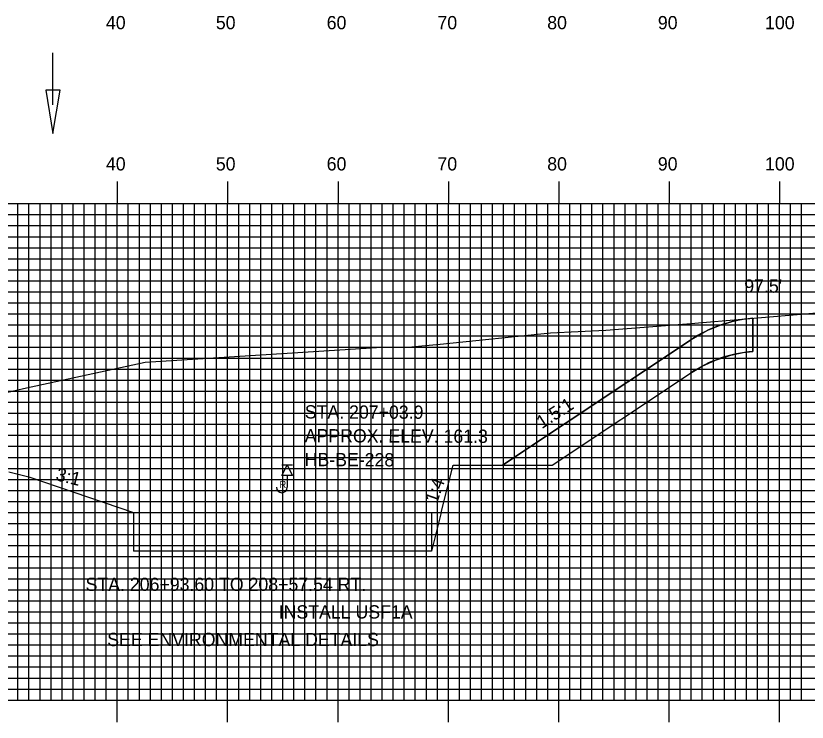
# Model space of a CAD drawing. Extents: x 1793666 to 1794009, y 442591 to 442811.
# Drawn here: x 1793862.1 to 1793933.8, y 442676.7 to 442740.7 of the extents above; entities that cross this region are included whole.
import ezdxf

# ---------------------------------------------------------------- set-up
doc = ezdxf.new("R2010")
doc.units = 0
for name, color, linetype in [('ANNOTATION', 7, 'Continuous'), ('BORING - REFUSAL', 7, 'Continuous'), ('D_Drainage_Ditch_Line', 7, 'Continuous'), ('D_Roadway_FinishedGrade', 7, 'Continuous'), ('D_Roadway_SlopeLines', 7, 'Continuous'), ('D_Roadway_SubGrade', 7, 'Continuous'), ('D_Text_Standard', 7, 'Continuous'), ('H_V ANNOTATION', 7, 'Continuous'), ('MAJOR', 7, 'Continuous'), ('MINOR', 7, 'Continuous'), ('S_Roadway_Centerline', 7, 'Continuous')]:
    doc.layers.add(name, color=color, linetype=linetype)

msp = doc.modelspace()

# ---------------------------------------------------------------- linework, layer by layer
at = {"layer": 'ANNOTATION'}
msp.add_line((1793907.099, 442699.959), (1793910.725, 442699.959), dxfattribs=at)
msp.add_line((1793907.099, 442699.959), (1793910.725, 442699.959), dxfattribs=at)
for points in [[(1793872.785, 442695.665), (1793873.01, 442695.665)], [(1793873.01, 442692.165), (1793872.785, 442692.165)]]:
    msp.add_lwpolyline(points, dxfattribs=at)
at = {"layer": 'BORING - REFUSAL'}
for p, q in [((1793887.193, 442699.965), (1793886.234, 442699.965)), ((1793886.714, 442699.006), (1793886.714, 442697.947))]:
    msp.add_line(p, q, dxfattribs=at)
msp.add_lwpolyline([(1793886.714, 442699.965), (1793887.193, 442699.006), (1793886.234, 442699.006)], close=True, dxfattribs=at)
msp.add_arc((1793886.229, 442697.947), 0.485, 180, 0, dxfattribs=at)
at = {"layer": 'D_Drainage_Ditch_Line'}
msp.add_line((1793865.488, 442732.626), (1793865.488, 442737.325), dxfattribs=at)
msp.add_lwpolyline([(1793866.144, 442733.939), (1793864.832, 442733.939), (1793865.488, 442730.002)], close=True, dxfattribs=at)
at = {"layer": 'D_Roadway_FinishedGrade'}
for p, q in [((1793928.899, 442713.269), (1793928.899, 442710.269)), ((1793873.01, 442695.665), (1793899.783, 442695.665)), ((1793899.783, 442695.665), (1793899.783, 442692.665))]:
    msp.add_line(p, q, dxfattribs=at)
for points in [[(1793906.224, 442699.959), (1793923.233, 442711.295)], [(1793910.725, 442699.959), (1793923.233, 442708.295)], [(1793899.783, 442692.665), (1793899.783, 442692.165), (1793873.01, 442692.165)]]:
    msp.add_lwpolyline(points, dxfattribs=at)
for centre in [(1793929.888, 442701.31), (1793929.888, 442698.31)]:
    msp.add_arc(centre, 12, 94.73004, 123.68465, dxfattribs=at)
at = {"layer": 'D_Roadway_SlopeLines'}
for p, q in [((1793900.658, 442695.665), (1793901.731, 442699.959)), ((1793901.731, 442699.959), (1793907.099, 442699.959)), ((1793900.658, 442695.665), (1793899.783, 442692.165))]:
    msp.add_line(p, q, dxfattribs=at)
msp.add_lwpolyline([(1793906.224, 442699.959), (1793910.725, 442699.959), (1793923.233, 442708.295), (1793924.295, 442708.927), (1793925.5, 442709.479), (1793926.888, 442709.929), (1793928.001, 442710.161), (1793928.899, 442710.269), (1793928.899, 442713.269), (1793928.006, 442713.161), (1793927.196, 442713.004), (1793925.983, 442712.656), (1793924.779, 442712.168), (1793923.233, 442711.295)], close=True, dxfattribs=at)
at = {"layer": 'D_Roadway_SubGrade'}
msp.add_line((1793861.488, 442699.354), (1793863.314, 442698.897), dxfattribs=at)
msp.add_lwpolyline([(1793863.314, 442698.897), (1793872.785, 442695.665), (1793872.785, 442692.165)], dxfattribs=at)
at = {"layer": 'MAJOR'}
for p, q in [((1793871.314, 442725.669), (1793871.314, 442723.665)), ((1793881.314, 442725.669), (1793881.314, 442723.665)), ((1793891.314, 442725.669), (1793891.314, 442723.665)), ((1793901.314, 442725.669), (1793901.314, 442723.665)), ((1793911.314, 442725.669), (1793911.314, 442723.665)), ((1793921.314, 442725.669), (1793921.314, 442723.665)), ((1793931.314, 442725.669), (1793931.314, 442723.665)), ((1793691.314, 442723.665), (1793971.314, 442723.665)), ((1793691.314, 442723.665), (1793971.314, 442723.665)), ((1793871.314, 442678.665), (1793871.314, 442723.665)), ((1793881.314, 442678.665), (1793881.314, 442723.665)), ((1793891.314, 442678.665), (1793891.314, 442723.665)), ((1793901.314, 442678.665), (1793901.314, 442723.665)), ((1793911.314, 442678.665), (1793911.314, 442723.665)), ((1793921.314, 442678.665), (1793921.314, 442723.665)), ((1793931.314, 442678.665), (1793931.314, 442723.665)), ((1793691.314, 442718.665), (1793971.314, 442718.665)), ((1793691.314, 442713.665), (1793971.314, 442713.665)), ((1793691.314, 442708.665), (1793971.314, 442708.665)), ((1793691.314, 442703.665), (1793971.314, 442703.665)), ((1793691.314, 442698.665), (1793971.314, 442698.665)), ((1793691.314, 442693.665), (1793971.314, 442693.665)), ((1793691.314, 442688.665), (1793971.314, 442688.665)), ((1793691.314, 442683.665), (1793971.314, 442683.665)), ((1793691.314, 442678.665), (1793971.314, 442678.665)), ((1793691.314, 442678.665), (1793971.314, 442678.665)), ((1793871.314, 442676.661), (1793871.314, 442678.665)), ((1793881.314, 442676.661), (1793881.314, 442678.665)), ((1793891.314, 442676.661), (1793891.314, 442678.665)), ((1793901.314, 442676.661), (1793901.314, 442678.665)), ((1793911.314, 442676.661), (1793911.314, 442678.665)), ((1793921.314, 442676.661), (1793921.314, 442678.665)), ((1793931.314, 442676.661), (1793931.314, 442678.665))]:
    msp.add_line(p, q, dxfattribs=at)
at = {"layer": 'MINOR'}
for p, q in [((1793862.314, 442678.665), (1793862.314, 442723.665)), ((1793863.314, 442678.665), (1793863.314, 442723.665)), ((1793864.314, 442678.665), (1793864.314, 442723.665)), ((1793865.314, 442678.665), (1793865.314, 442723.665)), ((1793866.314, 442678.665), (1793866.314, 442723.665)), ((1793867.314, 442678.665), (1793867.314, 442723.665)), ((1793868.314, 442678.665), (1793868.314, 442723.665)), ((1793869.314, 442678.665), (1793869.314, 442723.665)), ((1793870.314, 442678.665), (1793870.314, 442723.665)), ((1793872.314, 442678.665), (1793872.314, 442723.665)), ((1793873.314, 442678.665), (1793873.314, 442723.665)), ((1793874.314, 442678.665), (1793874.314, 442723.665)), ((1793875.314, 442678.665), (1793875.314, 442723.665)), ((1793876.314, 442678.665), (1793876.314, 442723.665)), ((1793877.314, 442678.665), (1793877.314, 442723.665)), ((1793878.314, 442678.665), (1793878.314, 442723.665)), ((1793879.314, 442678.665), (1793879.314, 442723.665)), ((1793880.314, 442678.665), (1793880.314, 442723.665)), ((1793882.314, 442678.665), (1793882.314, 442723.665)), ((1793883.314, 442678.665), (1793883.314, 442723.665)), ((1793884.314, 442678.665), (1793884.314, 442723.665)), ((1793885.314, 442678.665), (1793885.314, 442723.665)), ((1793886.314, 442678.665), (1793886.314, 442723.665)), ((1793887.314, 442678.665), (1793887.314, 442723.665)), ((1793888.314, 442678.665), (1793888.314, 442723.665)), ((1793889.314, 442678.665), (1793889.314, 442723.665)), ((1793890.314, 442678.665), (1793890.314, 442723.665)), ((1793892.314, 442678.665), (1793892.314, 442723.665)), ((1793893.314, 442678.665), (1793893.314, 442723.665)), ((1793894.314, 442678.665), (1793894.314, 442723.665)), ((1793895.314, 442678.665), (1793895.314, 442723.665)), ((1793896.314, 442678.665), (1793896.314, 442723.665)), ((1793897.314, 442678.665), (1793897.314, 442723.665)), ((1793898.314, 442678.665), (1793898.314, 442723.665)), ((1793899.314, 442678.665), (1793899.314, 442723.665)), ((1793900.314, 442678.665), (1793900.314, 442723.665)), ((1793902.314, 442678.665), (1793902.314, 442723.665)), ((1793903.314, 442678.665), (1793903.314, 442723.665)), ((1793904.314, 442678.665), (1793904.314, 442723.665)), ((1793905.314, 442678.665), (1793905.314, 442723.665)), ((1793906.314, 442678.665), (1793906.314, 442723.665)), ((1793907.314, 442678.665), (1793907.314, 442723.665)), ((1793908.314, 442678.665), (1793908.314, 442723.665)), ((1793909.314, 442678.665), (1793909.314, 442723.665)), ((1793910.314, 442678.665), (1793910.314, 442723.665)), ((1793912.314, 442678.665), (1793912.314, 442723.665)), ((1793913.314, 442678.665), (1793913.314, 442723.665)), ((1793914.314, 442678.665), (1793914.314, 442723.665)), ((1793915.314, 442678.665), (1793915.314, 442723.665)), ((1793916.314, 442678.665), (1793916.314, 442723.665)), ((1793917.314, 442678.665), (1793917.314, 442723.665)), ((1793918.314, 442678.665), (1793918.314, 442723.665)), ((1793919.314, 442678.665), (1793919.314, 442723.665)), ((1793920.314, 442678.665), (1793920.314, 442723.665)), ((1793922.314, 442678.665), (1793922.314, 442723.665)), ((1793923.314, 442678.665), (1793923.314, 442723.665)), ((1793924.314, 442678.665), (1793924.314, 442723.665)), ((1793925.314, 442678.665), (1793925.314, 442723.665)), ((1793926.314, 442678.665), (1793926.314, 442723.665)), ((1793927.314, 442678.665), (1793927.314, 442723.665)), ((1793928.314, 442678.665), (1793928.314, 442723.665)), ((1793929.314, 442678.665), (1793929.314, 442723.665)), ((1793930.314, 442678.665), (1793930.314, 442723.665)), ((1793932.314, 442678.665), (1793932.314, 442723.665)), ((1793933.314, 442678.665), (1793933.314, 442723.665)), ((1793691.314, 442722.665), (1793971.314, 442722.665)), ((1793691.314, 442721.665), (1793971.314, 442721.665)), ((1793691.314, 442720.665), (1793971.314, 442720.665)), ((1793691.314, 442719.665), (1793971.314, 442719.665)), ((1793691.314, 442717.665), (1793971.314, 442717.665)), ((1793691.314, 442716.665), (1793971.314, 442716.665)), ((1793691.314, 442715.665), (1793971.314, 442715.665)), ((1793691.314, 442714.665), (1793971.314, 442714.665)), ((1793691.314, 442712.665), (1793971.314, 442712.665)), ((1793691.314, 442711.665), (1793971.314, 442711.665)), ((1793691.314, 442710.665), (1793971.314, 442710.665)), ((1793691.314, 442709.665), (1793971.314, 442709.665)), ((1793691.314, 442707.665), (1793971.314, 442707.665)), ((1793691.314, 442706.665), (1793971.314, 442706.665)), ((1793691.314, 442705.665), (1793971.314, 442705.665)), ((1793691.314, 442704.665), (1793971.314, 442704.665)), ((1793691.314, 442702.665), (1793971.314, 442702.665)), ((1793691.314, 442701.665), (1793971.314, 442701.665)), ((1793691.314, 442700.665), (1793971.314, 442700.665)), ((1793691.314, 442699.665), (1793971.314, 442699.665)), ((1793691.314, 442697.665), (1793971.314, 442697.665)), ((1793691.314, 442696.665), (1793971.314, 442696.665)), ((1793691.314, 442695.665), (1793971.314, 442695.665)), ((1793691.314, 442694.665), (1793971.314, 442694.665)), ((1793691.314, 442692.665), (1793971.314, 442692.665)), ((1793691.314, 442691.665), (1793971.314, 442691.665)), ((1793691.314, 442690.665), (1793971.314, 442690.665)), ((1793691.314, 442689.665), (1793971.314, 442689.665)), ((1793691.314, 442687.665), (1793971.314, 442687.665)), ((1793691.314, 442686.665), (1793971.314, 442686.665)), ((1793691.314, 442685.665), (1793971.314, 442685.665)), ((1793691.314, 442684.665), (1793971.314, 442684.665)), ((1793691.314, 442682.665), (1793971.314, 442682.665)), ((1793691.314, 442681.665), (1793971.314, 442681.665)), ((1793691.314, 442680.665), (1793971.314, 442680.665)), ((1793691.314, 442679.665), (1793971.314, 442679.665))]:
    msp.add_line(p, q, dxfattribs=at)
at = {"layer": 'S_Roadway_Centerline'}
msp.add_lwpolyline([(1793861.293, 442706.545), (1793862.805, 442706.912), (1793873.831, 442709.284), (1793895.291, 442710.636), (1793898.005, 442710.675), (1793898.909, 442710.781), (1793900.58, 442710.922), (1793910.574, 442711.964), (1793915.574, 442712.181), (1793922.909, 442712.773), (1793934.327, 442713.718), (1793935.111, 442713.771), (1793936.514, 442713.888), (1793953.319, 442715.266), (1793970.122, 442716.692), (1793970.839, 442716.762), (1793971.093, 442716.785), (1793971.314, 442716.811)], dxfattribs=at)

# ---------------------------------------------------------------- texts
at = {"layer": 'ANNOTATION'}
for s, rotation, p in [('1.5:1', 32.76285, (1793909.781, 442703.214)), ('3:1', 345.96376, (1793865.673, 442698.603)), ('1:4', 70.51601, (1793900.269, 442696.421)), ('1:4', 70.51601, (1793900.269, 442696.421))]:
    msp.add_text(s, height=1.2, rotation=rotation, dxfattribs=at).set_placement(p)
at = {"layer": 'BORING - REFUSAL'}
for s, p in [('STA. 207+03.9', (1793888.3, 442704.189)), ('APPROX. ELEV. 161.3', (1793888.293, 442702.029)), ('HB-BE-228', (1793888.286, 442699.869))]:
    msp.add_text(s, height=1.2, rotation=359.81416, dxfattribs=at).set_placement(p)
msp.add_text('R', height=0.64, dxfattribs=at).set_placement((1793886.005, 442697.891))
at = {"layer": 'D_Text_Standard'}
for s, p in [("97.5'", (1793928.117, 442715.59)), ('STA. 206+93.60 TO 208+57.54 RT.', (1793868.443, 442688.557)), ('INSTALL USF1A', (1793885.937, 442686.057)), ('SEE ENVIRONMENTAL DETAILS', (1793870.404, 442683.557))]:
    msp.add_text(s, height=1.2, dxfattribs=at).set_placement(p)
at = {"layer": 'H_V ANNOTATION'}
for s, p in [('40', (1793870.286, 442739.465)), ('50', (1793880.243, 442739.465)), ('60', (1793890.286, 442739.465)), ('70', (1793900.318, 442739.465)), ('80', (1793910.264, 442739.465)), ('90', (1793920.286, 442739.465)), ('100', (1793929.997, 442739.465)), ('40', (1793870.286, 442726.665)), ('50', (1793880.243, 442726.665)), ('60', (1793890.286, 442726.665)), ('70', (1793900.318, 442726.665)), ('80', (1793910.264, 442726.665)), ('90', (1793920.286, 442726.665)), ('100', (1793929.997, 442726.665))]:
    msp.add_text(s, height=1.2, dxfattribs=at).set_placement(p)

doc.saveas('drawing.dxf')
